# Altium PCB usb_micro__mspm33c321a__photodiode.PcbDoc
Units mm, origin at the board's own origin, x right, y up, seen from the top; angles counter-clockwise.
Board outline 40.5 x 25 mm, 2 copper layers (Top, Bottom), stack 0 mm thick; 32 components, 20 nets, 150 pads, 49 vias.
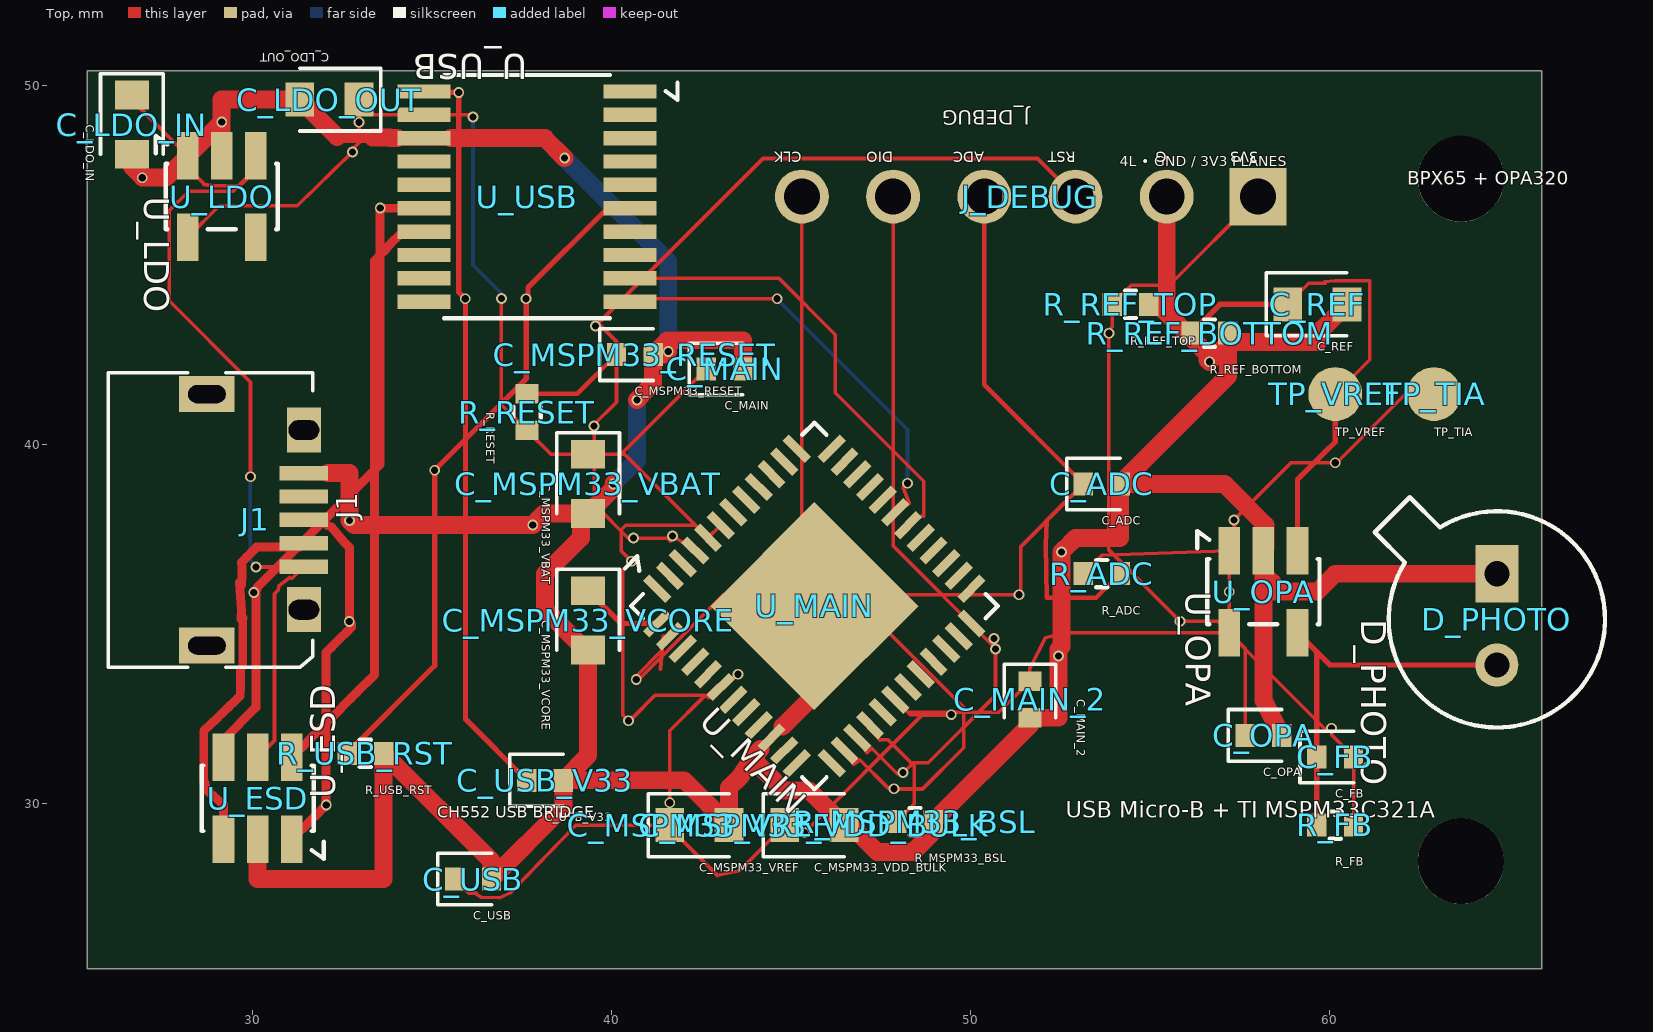
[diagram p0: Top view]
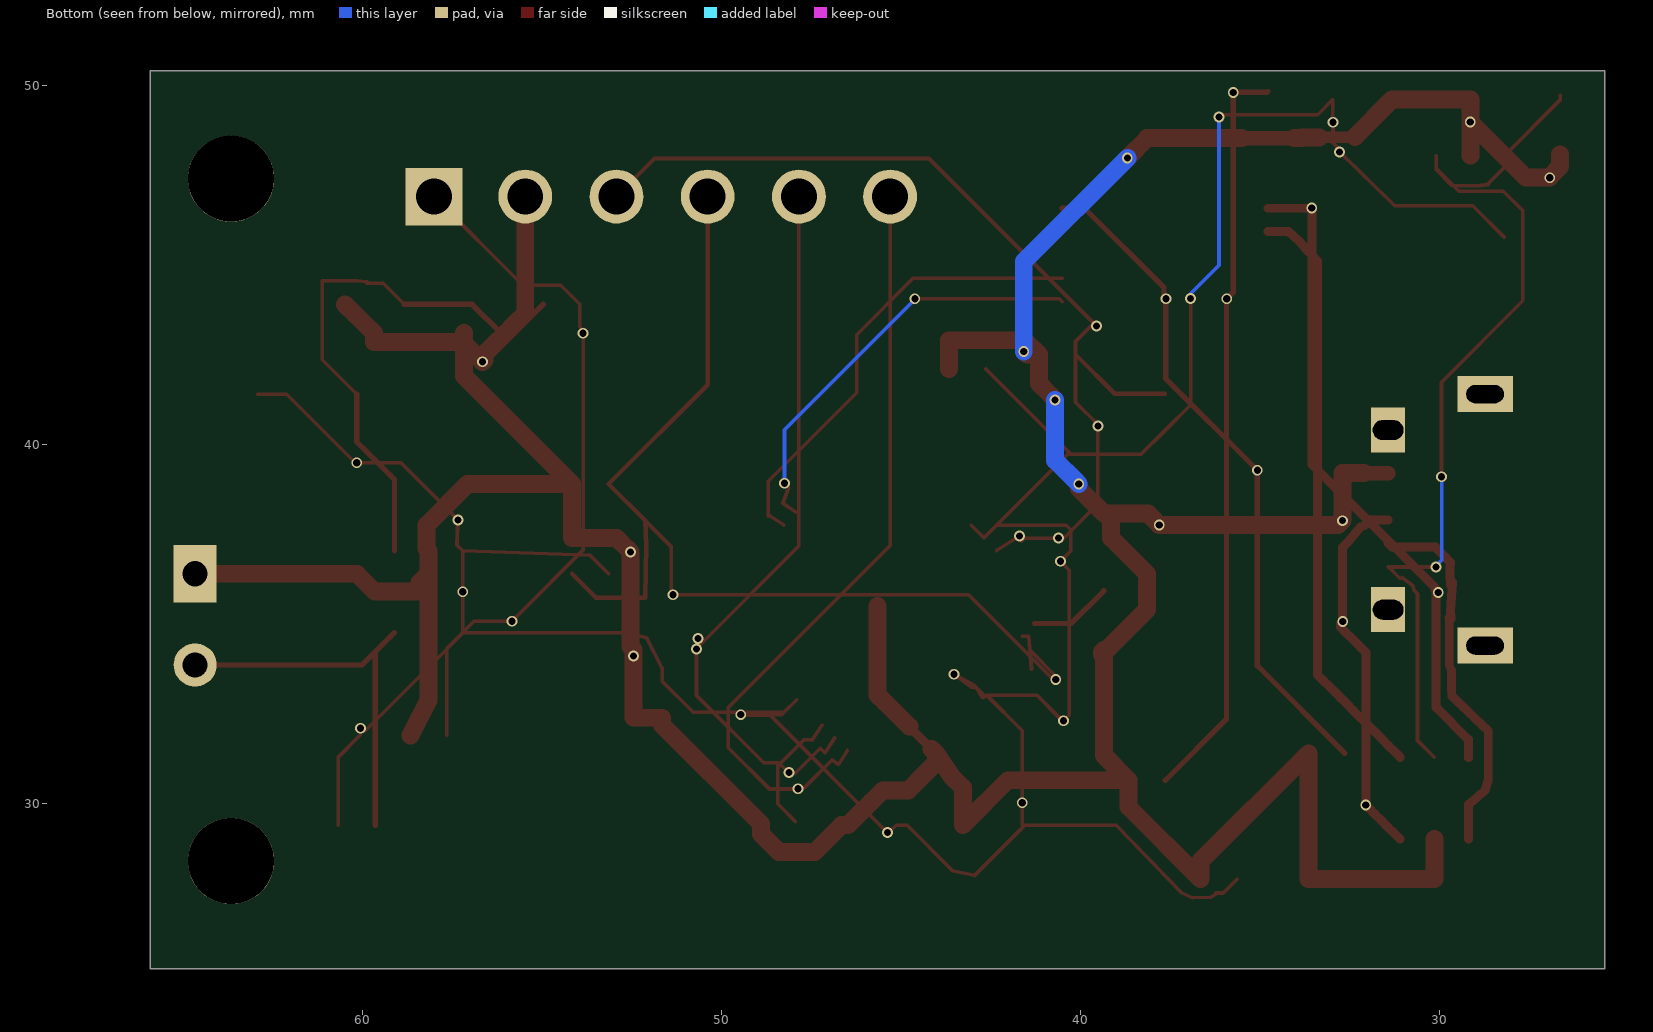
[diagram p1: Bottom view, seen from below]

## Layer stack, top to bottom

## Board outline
25.4,50.4 65.9,50.4 65.9,25.4 25.4,25.4

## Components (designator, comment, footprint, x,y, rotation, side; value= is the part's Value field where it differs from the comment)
C_ADC "" TSCIRCUIT-1.5600x0.6400mm 53.65,38.9 r0 top
C_FB "" TSCIRCUIT-1.5600x0.6400mm 60.15,31.3 r0 top
C_LDO_IN "" TSCIRCUIT-0.9500x2.4500mm 26.65,48.9 r270 top
C_LDO_OUT "" TSCIRCUIT-2.4500x0.9500mm 32.15,49.6 r180 top
C_MAIN "" TSCIRCUIT-1.5600x0.6400mm 43.15,42.1 r0 top
C_MAIN_2 "" TSCIRCUIT-0.6400x1.5600mm 51.65,32.9 r270 top
C_MSPM33_RESET "" TSCIRCUIT-1.5600x0.6400mm 40.65,42.5 r0 top
C_MSPM33_VBAT "" TSCIRCUIT-0.9500x2.4500mm 39.35,38.9 r270 top
C_MSPM33_VCORE "" TSCIRCUIT-0.9500x2.4500mm 39.35,35.1 r270 top
C_MSPM33_VDD_BULK "" TSCIRCUIT-2.4500x0.9500mm 45.65,29.4 r0 top
C_MSPM33_VREF "" TSCIRCUIT-2.4500x0.9500mm 42.45,29.4 r0 top
C_OPA "" TSCIRCUIT-1.5600x0.6400mm 58.15,31.9 r0 top
C_REF "" TSCIRCUIT-2.4500x0.9500mm 59.65,43.9 r0 top
C_USB "" TSCIRCUIT-1.5600x0.6400mm 36.15,27.9 r0 top
C_USB_V33 "" TSCIRCUIT-1.5600x0.6400mm 38.15,30.65 r0 top
D_PHOTO "" TSCIRCUIT-1.2000x3.9400mm 64.65,35.23 r270 top
J1 "" TSCIRCUIT-4.1500x8mm 30.037,37.9 r90 top
J_DEBUG "" TSCIRCUIT-14.2000x1.5000mm 51.65,46.9 r180 top
R_ADC "" TSCIRCUIT-1.5600x0.6400mm 53.65,36.4 r0 top
R_FB "" TSCIRCUIT-1.5600x0.6400mm 60.15,29.4 r0 top
R_MSPM33_BSL "" TSCIRCUIT-1.5600x0.6400mm 48.45,29.5 r0 top
R_REF_BOTTOM "" TSCIRCUIT-1.5600x0.6400mm 56.65,43.1 r0 top
R_REF_TOP "" TSCIRCUIT-1.5600x0.6400mm 54.45,43.9 r0 top
R_RESET "" TSCIRCUIT-0.6400x1.5600mm 37.65,40.9 r270 top
R_USB_RST "" TSCIRCUIT-1.5600x0.6400mm 33.15,31.4 r0 top
TP_TIA "" TSCIRCUIT-1.5000x1.5000mm 62.9,41.4 r0 top
TP_VREF "" TSCIRCUIT-1.5000x1.5000mm 60.15,41.4 r0 top
U_ESD "" TSCIRCUIT-2.5000x3.6000mm#1 30.15,30.15 r90 top
U_LDO "" TSCIRCUIT-2.5000x3.6000mm#2 29.15,46.9 r270 top
U_MAIN "" TSCIRCUIT-9.5459x9.5459mm 45.65,35.5 r315 top
U_OPA "" TSCIRCUIT-2.5000x3.6000mm#2 58.15,35.9 r270 top
U_USB "" TSCIRCUIT-7.2000x6.2500mm 37.65,46.9 r180 top

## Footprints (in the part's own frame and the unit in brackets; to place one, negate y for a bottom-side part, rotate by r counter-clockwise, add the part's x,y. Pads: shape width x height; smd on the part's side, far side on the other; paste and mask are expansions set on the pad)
TSCIRCUIT-0.6400x1.5600mm [mm]
  rect 0.54x0.64 smd: 1(-0.51,0) 2(0.51,0)
  silkscreen extent -0.98,-0.72 0.51,0.72
TSCIRCUIT-0.9500x2.4500mm [mm]
  rect 0.8x0.95 smd: 1(-0.825,0) 2(0.825,0)
  silkscreen extent -1.42,-0.87 0.83,0.87
TSCIRCUIT-1.2000x3.9400mm [mm]
  rect 1.6x1.2 hole 0.7: 1(-1.17,0)
  round 1.2 hole 0.7: 2(1.37,0)
  silkscreen extent -3.3,-3.4 3.11,3.01
TSCIRCUIT-1.5000x1.5000mm [mm]
  round 1.5 smd: 1(0,0)
TSCIRCUIT-1.5600x0.6400mm [mm]
  rect 0.54x0.64 smd: 1(-0.51,0) 2(0.51,0)
  silkscreen extent -0.98,-0.72 0.51,0.72
TSCIRCUIT-2.4500x0.9500mm [mm]
  rect 0.8x0.95 smd: 1(-0.825,0) 2(0.825,0)
  silkscreen extent -1.43,-0.87 0.82,0.87
TSCIRCUIT-2.5000x3.6000mm#1 [mm]
  rect 1.325x0.6 smd: 1(-1.138,-0.95) 2(-1.138,0) 3(-1.138,0.95) 4(1.137,0.95) 5(1.137,0) 6(1.137,-0.95)
  silkscreen extent -1.69,-1.84 0.91,1.56
TSCIRCUIT-2.5000x3.6000mm#2 [mm]
  rect 1.325x0.6 smd: 1(-1.138,-0.95) 2(-1.138,0) 3(-1.138,0.95) 4(1.138,0.95) 5(1.138,-0.95)
  silkscreen extent -1.69,-1.84 0.91,1.56
TSCIRCUIT-4.1500x8mm [mm]
  rect 0.4x1.35 smd: 1(-1.301,-1.4) 2(-0.65,-1.4) 3(0,-1.4) 4(0.65,-1.4) 5(1.3,-1.4)
  rect 1.25x0.95 hole 0.55 slot 0.85 at 90 deg: 6(2.5,-1.4) 7(-2.5,-1.4)
  rect 1x1.55 hole 0.5 slot 1.05 at 90 deg: 8(-3.5,1.3) 9(3.5,1.3)
  silkscreen extent -4.1,-1.65 4.1,4.05
TSCIRCUIT-7.2000x6.2500mm [mm]
  rect 1.475x0.4 smd: 1(-2.862,-2.925) 2(-2.862,-2.275) 3(-2.862,-1.625) 4(-2.862,-0.975) 5(-2.862,-0.325) 6(-2.862,0.325) 7(-2.862,0.975) 8(-2.862,1.625) 9(-2.862,2.275) 10(-2.862,2.925) 11(2.863,2.925) 12(2.863,2.275) 13(2.863,1.625) 14(2.863,0.975) 15(2.863,0.325) 16(2.863,-0.325) 17(2.863,-0.975) 18(2.863,-1.625) 19(2.863,-2.275) 20(2.863,-2.925)
  silkscreen extent -4.19,-3.38 2.31,3.38
TSCIRCUIT-9.5459x9.5459mm [mm]
  rect 0.875x0.25 smd: 1(-3.438,-2.75) 2(-3.438,-2.25) 3(-3.438,-1.75) 4(-3.438,-1.25) 5(-3.438,-0.75) 6(-3.438,-0.25) 7(-3.438,0.25) 8(-3.438,0.75) 9(-3.438,1.25) 10(-3.438,1.75) 11(-3.438,2.25) 12(-3.438,2.75) 25(3.438,2.75) 26(3.438,2.25) 27(3.438,1.75) 28(3.438,1.25) 29(3.438,0.75) 30(3.438,0.25) 31(3.438,-0.25) 32(3.438,-0.75) 33(3.438,-1.25) 34(3.438,-1.75) 35(3.438,-2.25) 36(3.438,-2.75)
  rect 0.25x0.875 smd: 13(-2.75,3.438) 14(-2.25,3.438) 15(-1.75,3.438) 16(-1.25,3.438) 17(-0.75,3.438) 18(-0.25,3.438) 19(0.25,3.438) 20(0.75,3.438) 21(1.25,3.438) 22(1.75,3.438) 23(2.25,3.438) 24(2.75,3.438) 37(2.75,-3.438) 38(2.25,-3.438) 39(1.75,-3.438) 40(1.25,-3.438) 41(0.75,-3.438) 42(0.25,-3.438) 43(-0.25,-3.438) 44(-0.75,-3.438) 45(-1.25,-3.438) 46(-1.75,-3.438) 47(-2.25,-3.438) 48(-2.75,-3.438)
  rect 4.1x4.1 smd: 49(0,0)
  silkscreen extent -4.47,-3.61 3.61,3.61
TSCIRCUIT-14.2000x1.5000mm [mm]
  rect 1.6x1.6 hole 1: 1(-6.35,0)
  round 1.5 hole 1: 2(-3.81,0) 3(-1.27,0) 4(1.27,0) 5(3.81,0) 6(6.35,0)

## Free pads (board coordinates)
  round 2.4 hole 2.4 unplated: NPTH-1(63.65,47.4) NPTH-2(63.65,28.4)

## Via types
v1: diameter 0.3, hole 0.2, Top to Bottom, 49 vias

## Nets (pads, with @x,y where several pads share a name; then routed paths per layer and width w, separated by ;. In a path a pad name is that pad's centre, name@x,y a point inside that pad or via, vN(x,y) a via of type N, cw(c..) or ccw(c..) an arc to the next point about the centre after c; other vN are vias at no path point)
".U_USB > .pin9 to .U_MAIN > .pin19": U_MAIN.19 U_USB.9 | length 13
  Top w0.1: U_USB.9 44.662,44.625 46.232,43.055 46.232,41.439 48.695,38.976 48.695,37.995 48.645,38.009 U_MAIN.19
".U_USB > .pin10 to .U_MAIN > .pin18": U_MAIN.18 U_USB.10 | length 11.9
  Top w0.1: U_USB.10 40.592,44.054 44.363,44.054 v1(44.613,44.054) ; U_MAIN.18 48.29,38.361 48.125,38.8 v1(48.242,38.917)
  Bottom w0.1: v1(44.613,44.054) 44.703,43.964 44.703,43.95 48.242,40.411 v1(48.242,38.917)
ADC_IN: C_ADC.1 J_DEBUG.4 R_ADC.2 U_MAIN.47 | length 33.3
  Top w0.1: U_MAIN.47 41.443,34.653 41.367,33.745 41.397,34.262 41.381,34.237 41.377,34.232 40.689,33.545 v1(40.689,33.454) 40.724,33.419 43.118,35.814 v1(51.343,35.814) 51.4,35.871 51.4,37.16 C_ADC.1
  Top w0.12: J_DEBUG.4 50.38,41.66 C_ADC.1 52.12,37.88 52.09,37.195 52.12,35.733 53.493,35.733 R_ADC.2
GND: C_ADC.2 C_LDO_IN.2 C_LDO_OUT.2 C_MAIN.2 C_MAIN_2.2 C_MSPM33_RESET.2 C_MSPM33_VBAT.2 C_MSPM33_VCORE.2 C_MSPM33_VDD_BULK.2 C_MSPM33_VREF.2 C_OPA.2 C_REF.2 C_USB.2 C_USB_V33.2 D_PHOTO.1 J1.5 J_DEBUG.2 R_MSPM33_BSL.2 R_REF_BOTTOM.2 R_USB_RST.2 U_ESD.2 U_LDO.2 U_MAIN.39 U_MAIN.49 U_OPA.2 U_USB.18 | length 133.1
  Top w0.25: U_MAIN.39@44.766,32.141 U_MAIN.39 ; U_MAIN.39 44.147,31.523 U_MAIN.39
  Top w0.325: 32.364,48.561 32.4,48.561 32.878,48.553 33.355,48.546
  Top w0.4: J1.5 J1.5@32.113,39.2 ; U_USB.18@34.05,48.525 U_USB.18 34.913,48.525 35.038,48.525 35.163,48.525 35.288,48.525 35.413,48.525 U_USB.18@35.525,48.525
  Top w0.5: C_LDO_IN.2 26.65,47.733 26.938,47.445 v1(26.938,47.425) 27.598,47.425 v1(29.15,48.977) U_LDO.2 ; U_LDO.2 29.15,49.6 C_LDO_OUT.2 32.364,48.561 ; U_ESD.2 30.15,27.9 33.66,27.9 R_USB_RST.2 36.66,28.4 C_USB.2 38.66,29.9 C_USB_V33.2 ; 32.113,39.2 32.706,39.2 v1(32.706,37.878) 32.742,37.842 32.829,37.755 33.327,37.755 33.825,37.755 34.324,37.755 34.822,37.755 35.32,37.755 35.818,37.755 36.316,37.755 36.815,37.755 37.313,37.755 v1(37.811,37.755) 37.931,37.875 37.931,37.88 38.126,38.075 38.534,38.075 38.942,38.075 C_MSPM33_VBAT.2 ; 33.355,48.546 33.833,48.539 33.847,48.525 34.05,48.525 ; 35.525,48.525 35.538,48.525 35.663,48.525 35.788,48.525 38.145,48.525 v1(38.697,47.973) ; v1(40.05,38.9) 40.05,38.775 C_MSPM33_VBAT.2 ; v1(40.708,41.236) 40.842,41.37 40.842,41.382 41.16,41.7 C_MSPM33_RESET.2 ; v1(41.581,42.587) 41.494,42.5 C_MSPM33_RESET.2 ; C_MAIN.2 43.66,42.9 41.56,42.9 C_MSPM33_RESET.2 ; 44.766,32.141 45.438,32.813 45.65,33.025 U_MAIN.49 ; J_DEBUG.2 55.46,46.436 55.46,45.971 55.46,45.507 55.46,45.042 55.46,44.578 55.46,44.114 55.46,43.649 55.744,43.365 56.028,43.082 56.311,42.798 56.595,42.514 56.595,42.355 v1(56.65,42.3) 57.16,42.81 R_REF_BOTTOM.2 ; C_OPA.2 58.15,32.873 58.15,33.336 58.15,33.798 58.15,34.261 58.15,34.724 58.15,35.187 58.15,35.649 58.15,36.112 58.15,36.575 U_OPA.2 ; C_REF.2 60.208,43.633 59.942,43.367 59.675,43.1 59.675,42.85 57.16,42.85 R_REF_BOTTOM.2 ; D_PHOTO.1 60.15,36.4 59.65,35.9 58.4,35.9 58.4,36.15 58.15,36.4 U_OPA.2 ; C_USB_V33.2 39.35,31.34 C_MSPM33_VCORE.2 39.4,34.225 39.4,34.15 38.15,35.4 38.15,36.4 39.15,37.4 39.15,37.9 39.325,38.075 C_MSPM33_VBAT.2 ; C_USB_V33.2 42.025,30.65 C_MSPM33_VREF.2 43.275,29.748 43.275,30.096 43.275,30.443 43.591,30.76 44.025,31.4 44.025,31.141 44.329,30.837 44.796,30.37 45.505,30.37 45.829,30.046 46.152,29.723 C_MSPM33_VDD_BULK.2 46.65,29.4 47.4,28.65 48.4,28.65 48.9,29.15 48.9,29.44 R_MSPM33_BSL.2 51.65,32.19 C_MAIN_2.2 52.444,32.39 v1(52.444,34.11) 52.448,34.114 52.448,34.291 52.528,34.371 52.528,34.811 52.528,35.25 52.528,35.689 52.528,36.128 52.528,36.568 v1(52.528,37.007) 52.605,37.084 52.916,37.395 54.16,37.395 C_ADC.2 ; C_ADC.2 57.063,38.9 58.213,37.751 58.213,37.1 U_OPA.2 ; C_ADC.2 57.16,41.9 R_REF_BOTTOM.2 ; 44.025,31.4 44.147,31.523 44.025,31.4
  Bottom w0.5: v1(38.697,47.973) 41.581,45.089 v1(41.581,42.587) ; v1(40.05,38.9) 40.128,38.978 40.708,39.558 v1(40.708,41.236)
MAIN_RESET: C_MSPM33_RESET.1 J_DEBUG.3 R_RESET.1 U_MAIN.4 | length 27.8
  Top w0.1: C_MSPM33_RESET.1 40.14,41.175 39.497,40.532 v1(39.517,40.512) 39.517,38.339 40.54,37.317 v1(40.615,37.392) 41.55,37.392 41.634,37.308 41.654,37.475 v1(41.7,37.45) U_MAIN.4
  Top w0.12: R_RESET.1 39.05,41.41 C_MSPM33_RESET.1 40.14,42.864 39.706,43.298 39.558,43.298 44.22,47.96 51.86,47.96 J_DEBUG.3
  other v1: 39.558,43.298
MSPM33_BSL_INVOKE: R_MSPM33_BSL.1 U_MAIN.33 | length 3.5
  Top w0.1: U_MAIN.33 47.473,31.763 47.486,31.779 47.699,31.779 48.433,31.046 48.432,29.992 R_MSPM33_BSL.1
MSPM33_SWCLK: J_DEBUG.6 U_MAIN.35 | length 21.6
  Top w0.1: J_DEBUG.6 45.3,37.186 49.745,32.741 49.808,32.678 49.808,31.556 48.659,30.408 48.058,30.408 47.926,30.408 v1(47.869,30.414) 47.686,30.447 46.912,31.221 46.744,31.093 U_MAIN.35
MSPM33_SWDIO: J_DEBUG.5 U_MAIN.34 | length 21
  Top w0.1: U_MAIN.34 47.117,31.413 47.249,31.542 47.959,30.832 v1(48.118,30.865) 48.17,30.901 48.408,31.139 48.818,31.139 50.691,33.012 v1(50.691,34.301) v1(50.65,34.6) 50.687,34.305 50.687,34.329 47.84,37.177 J_DEBUG.5
MSPM33_VCORE: C_MSPM33_VCORE.1 U_MAIN.48 | length 2.3
  Top w0.15: C_MSPM33_VCORE.1 40.261,35.014 U_MAIN.48
PD_SUM: C_FB.1 D_PHOTO.2 R_FB.1 U_OPA.4 | length 11.5
  Top w0.15: R_FB.1 C_FB.1 59.64,34.222 U_OPA.4 60.002,33.86 D_PHOTO.2
TIA_OUT: C_FB.2 R_ADC.1 R_FB.2 TP_TIA.1 U_OPA.1 | length 21.5
  Top w0.1: R_ADC.1 53.65,36.91 U_OPA.1 ; R_FB.2 C_FB.2 60.05,31.91 v1(60.05,32.1) 59.976,32.026 59.914,32.026 57.2,34.74 v1(57.2,35.9) 57.2,36.038 U_OPA.1 ; TP_TIA.1 62.1,41.4 60.191,39.491 v1(60.153,39.491) 58.918,39.491 57.47,38.043 57.47,38.033 v1(57.335,37.898) 57.36,37.197 U_OPA.1
USB_BRIDGE_RESET: R_USB_RST.1 U_USB.6 | length 18.8
  Top w0.15: R_USB_RST.1 35.078,33.838 v1(35.078,39.279) 35.136,39.337 37.624,41.825 v1(37.624,44.055) 37.678,44.109 37.678,44.365 39.888,46.575 U_USB.6
USB_BRIDGE_V33: C_USB_V33.1 U_USB.20 | length 20.9
  Top w0.15: U_USB.20 34.813,49.8 v1(35.75,49.8) 35.75,49.778 35.75,44.235 v1(35.931,44.054) 35.936,44.049 35.936,32.354 C_USB_V33.1
USB_DM_MCU: U_ESD.4 U_USB.15 | length 18.4
  Top w0.25: U_ESD.4 29.2,31.778 30.1,32.678 30.1,35.823 v1(30.044,35.879) 30.126,35.961 30.126,36.007 33.561,39.441 v1(33.561,46.583) 33.569,46.575 33.787,46.575 U_USB.15
USB_DM_PORT: J1.2 U_ESD.3 | length 10.5
  Top w0.238: 29.675,33.712 29.736,33.853 29.736,34.072 29.736,34.291 29.736,34.509 29.736,34.728 29.736,34.947 29.736,35.166
  Top w0.25: U_ESD.3 29.2,29.252 29.2,29.491 29.2,29.731 29.2,29.97 29.051,30.096 28.901,30.221 28.752,30.346 28.65,30.65 28.65,32.025 29.033,32.386 29.191,32.539 29.349,32.692 29.508,32.845 29.666,32.999 29.669,33.237 29.672,33.475 29.675,33.712 ; 29.736,35.166 29.694,35.14 29.697,35.378 29.65,36.15 29.706,36.092 29.709,36.329 29.712,36.567 29.702,36.719 29.843,36.859 29.984,37 30.125,37.141 30.366,37.141 30.607,37.141 30.847,37.141 31.088,37.141 31.329,37.141 J1.2
USB_DP_MCU: U_ESD.6 U_USB.14 | length 16.5
  Top w0.25: U_ESD.6 31.265,31.452 31.429,31.617 31.594,31.781 31.758,31.946 31.923,32.11 32.087,32.275 32.252,32.439 32.416,32.604 32.581,32.768 32.746,32.933 32.91,33.097 33.075,33.262 33.239,33.426 33.404,33.591 33.404,33.836 33.404,34.081 33.404,34.326 33.404,34.571 33.404,34.817 33.404,35.062 33.404,35.307 33.404,35.552 33.404,35.797 33.404,36.042 33.404,36.287 33.404,36.533 33.404,36.778 33.404,37.023 33.404,37.268 33.404,37.513 33.404,37.758 33.404,38.004 33.404,38.249 33.404,38.494 33.404,38.739 33.404,38.984 33.404,39.229 33.404,39.475 33.404,39.72 33.404,39.965 33.404,40.21 33.404,40.455 33.404,40.7 33.404,40.946 33.404,41.191 33.404,41.436 33.404,41.681 33.404,41.926 33.404,42.171 33.404,42.416 33.404,42.662 33.404,42.907 33.404,43.152 33.404,43.397 33.404,43.642 33.404,43.887 33.404,44.133 33.404,44.378 33.404,44.623 33.404,44.868 33.404,45.113 33.566,45.276 33.728,45.438 33.9,45.65 34.216,45.925 34.406,45.925 34.597,45.925 U_USB.14
USB_DP_PORT: J1.3 U_ESD.1 | length 10.4
  Top w0.25: U_ESD.1 31.107,29.012 31.281,29.187 31.455,29.361 31.63,29.536 31.804,29.71 31.978,29.884 v1(32.058,29.964) 32.058,30.214 32.058,30.463 32.058,30.713 32.058,30.963 32.058,31.212 32.058,31.462 32.058,31.712 32.058,31.961 32.058,32.211 32.058,32.461 32.058,32.71 32.058,32.96 32.058,33.209 32.058,33.459 32.058,33.709 32.058,33.958 32.058,34.208 32.2,34.35 32.342,34.492 32.484,34.634 32.626,34.777 32.769,34.919 32.769,35.002 v1(32.703,35.068) 32.703,35.297 32.703,35.526 32.703,35.756 32.703,35.985 32.703,36.214 32.703,36.443 32.703,36.672 32.703,36.902 32.703,37.131 32.549,37.284 32.2,37.7 32.089,37.745 31.935,37.899 31.687,37.899 31.439,37.899 J1.3
VBUS5: C_LDO_IN.1 J1.1 U_ESD.5 U_LDO.1 U_LDO.3 | length 26.8
  Top w0.1: C_LDO_IN.1 26.65,49.588 U_LDO.1 28.2,47.714 28.68,47.234 28.656,47.236 28.853,47.208 29.25,47.205 29.45,47.202 29.672,47.215 30.1,47.643 U_LDO.3 30.1,47.684 29.466,47.05 28.228,47.05 27.69,46.512 27.69,43.996 29.951,41.735 29.951,39.236 v1@29.951,39.101 ; v1(30.108,36.587) 31.426,36.587 J1.1 31.114,36.276 31.073,36.276 31.04,36.297 30.737,36.057 30.719,35.94 30.621,35.841 30.621,35.73 30.621,31.758 U_ESD.5
  Bottom w0.1: v1(29.95,39.1) 29.95,36.771 30.069,36.652 30.069,36.626 v1(30.108,36.587)
VCC_3V3: C_LDO_OUT.1 C_MAIN.1 C_MAIN_2.1 C_MSPM33_VBAT.1 C_MSPM33_VDD_BULK.1 C_MSPM33_VREF.1 C_OPA.1 C_USB.1 J_DEBUG.1 R_REF_TOP.1 R_RESET.2 U_LDO.5 U_MAIN.5 U_MAIN.6 U_MAIN.31 U_MAIN.43 U_OPA.5 U_USB.19 | length 97.4
  Top w0.1: U_LDO.5 29.083,46.645 31.249,46.645 v1(32.788,48.14) 32.845,48.241 32.845,48.269 32.973,48.397 v1(32.973,48.967) 32.96,48.978 32.931,48.978 32.975,49.022 C_LDO_OUT.1 33.4,49.175 U_USB.19 36.037,49.175 36.09,49.175 v1(36.146,49.119) ; C_USB.1 36.028,27.512 36.228,27.512 36.197,27.499 36.384,27.394 36.883,27.374 37.198,27.526 39.01,29.4 C_MSPM33_VREF.1 ; v1(36.936,44.059) 36.936,41.104 R_RESET.2 38.315,39.725 C_MSPM33_VBAT.1 ; C_MAIN.1 40.265,39.725 C_MSPM33_VBAT.1 ; U_MAIN.5 U_MAIN.6 ; 55.658,35.25 v1(55.832,35.076) 56.886,35.076 U_OPA.5 ; 55.658,35.251 53.85,37.059 v1(53.85,43.097) 53.85,43.187 53.94,43.277 R_REF_TOP.1 54.47,44.43 55.53,44.43 J_DEBUG.1 ; C_OPA.1 57.64,34.322 U_OPA.5 ; C_MSPM33_VBAT.1 40.364,39.725 U_MAIN.5 42.337,37.753 40.4,37.753 40.274,37.627 40.274,37.032 v1(40.558,36.748) 40.311,36.501 40.311,36.236 40.311,32.465 v1(40.471,32.305) 40.564,32.398 40.6,32.398 41.215,33.013 42.603,33.013 42.724,32.945 42.891,33.216 U_MAIN.43 v1(43.525,33.6) 42.968,33.293 42.655,32.991 42.603,33.011 41.625,32.033 v1(41.625,30.025) C_MSPM33_VREF.1 ; C_MSPM33_VREF.1 41.6,29.35 42.95,28 43.575,28.136 C_MSPM33_VDD_BULK.1 45.134,29.4 45.278,29.256 45.312,29.256 v1(45.375,29.193) 48.647,32.465 49.449,32.465 v1(49.461,32.477) 48.32,32.477 U_MAIN.31 48.257,32.54 50.78,32.54 C_MAIN_2.1 51.65,33.779 52.08,34.616 52.626,34.755 57.193,34.755 U_OPA.5
  Bottom w0.1: v1(36.146,49.119) 36.146,44.992 36.939,44.199 36.939,44.062 v1(36.936,44.059)
VREF_0V5: C_REF.1 R_REF_BOTTOM.1 R_REF_TOP.2 TP_VREF.1 U_OPA.3 | length 15.5
  Top w0.1: C_REF.1 59.411,44.486 59.867,44.486 59.855,44.532 60.151,44.554 60.351,44.555 60.651,44.556 60.851,44.556 61.109,44.55 61.108,42.358 TP_VREF.1
  Top w0.15: R_REF_TOP.2 55.76,43.1 R_REF_BOTTOM.1 56.94,43.9 C_REF.1 ; U_OPA.3 59.1,39.021 59.853,39.774 60.15,40.071 TP_VREF.1
pads on no net: J1.4 J1.6 J1.7 J1.8 J1.9 U_LDO.4 U_MAIN.1 U_MAIN.2 U_MAIN.3 U_MAIN.7 U_MAIN.8 U_MAIN.9 U_MAIN.10 U_MAIN.11 U_MAIN.12 U_MAIN.13 U_MAIN.14 U_MAIN.15 U_MAIN.16 U_MAIN.17 U_MAIN.20 U_MAIN.21 U_MAIN.22 U_MAIN.23 U_MAIN.24 U_MAIN.25 U_MAIN.26 U_MAIN.27 U_MAIN.28 U_MAIN.29 U_MAIN.30 U_MAIN.32 U_MAIN.36 U_MAIN.37 U_MAIN.38 U_MAIN.40 U_MAIN.41 U_MAIN.42 U_MAIN.44 U_MAIN.45 U_MAIN.46 U_USB.1 U_USB.2 U_USB.3 U_USB.4 U_USB.5 U_USB.7 U_USB.8 U_USB.11 U_USB.12 U_USB.13 U_USB.16 U_USB.17

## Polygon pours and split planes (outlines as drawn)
GND on Mid1 (solid): 35.488,50.1 25.7,50.1 25.7,25.7 65.6,25.7 65.6,50.1 36.012,50.1 36.033,50.083 36.083,50.022 36.12,49.953 36.142,49.878 36.15,49.8 36.142,49.722 36.12,49.647 36.083,49.578 36.033,49.517 36.025,49.511 36.025,49.498 36.068,49.511 36.146,49.519 36.224,49.511 36.299,49.489 36.368,49.452 36.429,49.402 36.479,49.341 36.516,49.272 36.538,49.197 36.546,49.119 36.538,49.041 36.516,48.966 36.479,48.897 36.429,48.836 36.368,48.786 36.299,48.749 36.224,48.727 36.146,48.719 36.068,48.727 36.025,48.74 36.025,44.441 36.084,44.424 36.153,44.387 36.214,44.337 36.264,44.276 36.301,44.207 36.323,44.132 36.331,44.054 36.323,43.976 36.301,43.901 36.264,43.832 36.214,43.771 36.153,43.721 36.084,43.684 36.009,43.662 35.931,43.654 35.853,43.662 35.778,43.684 35.709,43.721 35.648,43.771 35.598,43.832 35.561,43.901 35.539,43.976 35.531,44.054 35.532,44.069 35.521,44.082 35.496,44.13 35.48,44.181 35.475,44.235 35.475,49.511 35.467,49.517 35.417,49.578 35.38,49.647 35.358,49.722 35.35,49.8 35.358,49.878 35.38,49.953 35.417,50.022 35.467,50.083
VCC_3V3 on Mid2 (solid): 65.6,50.1 25.7,50.1 25.7,25.7 65.6,25.7

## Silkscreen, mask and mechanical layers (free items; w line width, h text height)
Top Overlay:
  text "4L • GND / 3V3 PLANES" at 54.15,47.65 h0.48
  text "BPX65 + OPA320" at 62.15,47.1 h0.65
  text "CH552 USB BRIDGE" at 35.15,29.5 h0.55
  text "USB Micro-B + TI MSPM33C321A" at 52.65,29.45 h0.78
